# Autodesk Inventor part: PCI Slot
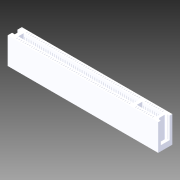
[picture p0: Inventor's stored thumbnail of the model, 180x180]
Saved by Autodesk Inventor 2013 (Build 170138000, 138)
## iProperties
Company: Autodesk Inc.
Created: 2005-12
Part Number: PCI Slot
Document SubType Name: Modeling
Designer: Autodesk Inc.
Density: 1 g/cm^3
Mass: 7.81096 g
Surface Area: 89.1874 cm^2
Volume: 7.81096 cm^3
Material: Allgemein
Title: Personal Computer
Author: Autodesk Inc.
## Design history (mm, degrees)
sketch "Sketch1"
  geometry: L1 (0, 5.6)-(0, -5.6) reference; L2 (-59.5, 0)-(59.5, 0) reference; L3 (-42.5, 4)-(42.5, 4); L4 (42.5, 4)-(42.5, -4); L5 (42.5, -4)-(-42.5, -4); L6 (-42.5, -4)-(-42.5, 4)
  constraints: 8 end point, 2 parallel, 1 horizontal, 1 perpendicular, 2 other
  dimensions: "d0" = 85 distance of L3.start L3.end; "d1" = 8 distance of L5.end L3.start
extrude "Extrusion1" new body sketch "Sketch1" distance "d2" = 15; taper "d3" = 0 deg
sketch "Sketch2"
  geometry: L1 (42.5, 4)-(42.5, -4) reference; L2 (-42.5, -4)-(-42.5, 4) reference; L3 (-42.5, 0)-(42.5, 0); L4 (-42.5, 1.5)-(-41, 1.5); L5 (-41, 1.5)-(-41, -1.5); L6 (-41, -1.5)-(-42.5, -1.5); L7 (-42.5, -1.5)-(-42.5, 1.5); L8 (42.5, 2.5)-(41.9, 2.5); L9 (40.7, 1.3)-(40.7, -1.3); L10 (41.9, -2.5)-(42.5, -2.5); L11 (42.5, -2.5)-(42.5, 2.5); A1 r 1.2 centre (41.9, 1.3) between (41.9, 2.5) and (40.7, 1.3); A2 r 1.2 centre (41.9, -1.3) between (40.7, -1.3) and (41.9, -2.5); 2 further points
  constraints: 18 end point, 6 point on line, 4 parallel, 4 point on circle, 4 tangent, 2 centre point, 2 horizontal, 2 midpoint, 2 perpendicular, 1 equal radius, 2 other
  dimensions: "d4" = 3 distance of L4.end L5.end; "d5" = 1.5 distance of L4.start L4.end; "d6" = 1.8 distance of L8.start point (40.7, 2.5); "d7" = 5 distance of point (40.7, 2.5) point (40.7, -2.5); "d8" = 1.2 radius of A1
extrude "Extrusion2" cut sketch "Sketch2" distance "d9" = 12; taper "d10" = 0 deg
sketch "Sketch3"
  geometry: L1 (40.7, -1.3)-(40.7, 1.3) reference; L2 (-42.5, 4)-(42.5, 4) reference; L3 (-42.5, 1.5)-(-42.5, 4) reference; L4 (-42.5, 1.5)-(-41, 1.5) reference; L5 (-41, 1.5)-(-41, -1.5) reference; L6 (-41, 0)-(40.7, 0); L7 (-39, 1.5)-(26, 1.5); L8 (26, 1.5)-(26, -1.5); L9 (26, -1.5)-(-39, -1.5); L10 (-39, -1.5)-(-39, 1.5); L11 (28, 1.5)-(39.2, 1.5); L12 (39.2, 1.5)-(39.2, -1.5); L13 (39.2, -1.5)-(28, -1.5); L14 (28, -1.5)-(28, 1.5); L15 (-40.634, 3)-(-41.933, 2.25); L16 (-41.933, 2.25)-(-41.933, 3.75); L17 (-41.933, 3.75)-(-40.634, 3); 1 further point
  constraints: 24 end point, 5 parallel, 2 horizontal, 2 midpoint, 2 perpendicular, 1 collinear, 1 vertical, 7 other
  dimensions: "d11" = 2 distance between parallel lines of L14 L8; "d12" = 2 distance between parallel lines of L5 L10; "d13" = 65 distance of L7.start L7.end; "d14" = 1.5 distance between parallel lines of L1 L12; "d15" = 1 distance from line of L3 point (-41.5, 3) (= d16); "d16" = 1 distance from line of point (-41.5, 3) L2; "d17" = 1.5 distance of L15.end L16.end
extrude "Extrusion3" cut sketch "Sketch3" distance "d18" = 8; taper "d19" = 0 deg
extrude "Extrusion4" cut sketch "Sketch3" distance "d20" = 0.1; taper "d21" = 0 deg
sketch "Sketch4"
  geometry: L1 (-42.5, 1.5)-(-42.5, 4) reference; L2 (-41, 1.5)-(-41, -1.5) reference; L3 (-42.5, 2.75)-(-33.115, 2.75); L4 (-38.5, 3.25)-(-38.25, 3.25); L5 (-38.25, 3.25)-(-38.25, 2.25); L6 (-38.25, 2.25)-(-38.5, 2.25); L7 (-38.5, 2.25)-(-38.5, 3.25); L8 (-41, 0)-(-34.959, 0); L9 (-38.25, -2.25)-(-38.5, -2.25); L10 (-38.5, -2.25)-(-38.5, -3.25); L11 (-38.5, -3.25)-(-38.25, -3.25); L12 (-38.25, -3.25)-(-38.25, -2.25)
  constraints: 20 end point, 4 symmetric about line, 3 perpendicular, 2 midpoint, 2 parallel, 1 horizontal, 1 other
  dimensions: "d22" = 0.25 distance of L4.start L4.end; "d23" = 1 distance of L4.end L5.end; "d24" = 4 distance between parallel lines of L1 L7
extrude "Extrusion5" cut sketch "Sketch4" distance "d25" = 8; taper "d26" = 0 deg
sketch "Sketch5"
  geometry: L1 (0.25, 0)-(0, 0) reference; L2 (0.25, 8)-(0.25, 0) reference; L3 (0, 8)-(0.25, 8) reference; L4 (0, 8)-(0, 0) reference; L5 (0, 6.5)-(0.25, 6.5)
  constraints: 2 end point, 2 point on line, 1 perpendicular
  dimensions: "d27" = 1.5 distance between parallel lines of L5 L3
extrude "Extrusion6" cut sketch "Sketch5" stored distance "d28" = 8; taper "d29" = 0 deg
body "Solid1"
pattern_linear "Rectangular Pattern1" dims "d32" = 1.2
